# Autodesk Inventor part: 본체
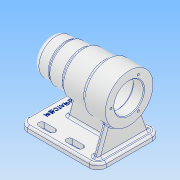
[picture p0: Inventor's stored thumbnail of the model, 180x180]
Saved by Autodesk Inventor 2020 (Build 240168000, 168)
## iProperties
Created: 2021-10
Part Number: 본체
Material: 알루미늄 6061
Document SubType Name: Modeling
Designer: user
Density: 2.7 g/cm^3
Appearance: 알루미늄 - 평지
Mass: 694.197 g
Surface Area: 698.877 cm^2
Volume: 257.11 cm^3
Author: user
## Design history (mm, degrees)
sketch "스케치1"
  geometry: L1 (0, 0)-(0, 25); L2 (0, 25)-(24, 25); L3 (112, 21)-(97, 21); L4 (97, 21)-(97, 21); L5 (94, 24)-(46, 24); L6 (43, 21)-(43, 21); L7 (43, 21)-(31.3, 21); L8 (31, 20.7)-(31, 17.5); L9 (31, 17.5)-(13.3, 17.5); L10 (13, 17.2)-(13, 16); L11 (13, 16)-(9.3, 16); L12 (9, 15.7)-(9, 10.5); L13 (9, 10.5)-(9, 10.5); L14 (6, 7.5)-(6, 0); L15 (6, 0)-(0, 0); L16 (24, 25)-(24, 27); L17 (24, 27)-(46, 27); L18 (46, 27)-(46, 30); L19 (80, 34)-(112, 34); L20 (112, 34)-(112, 21); L21 (46, 30)-(80, 30); L22 (80, 30)-(80, 34); A1 r 0.3 centre (9.3, 15.7) between (9.3, 16) and (9, 15.7); A2 r 0.3 centre (13.3, 17.2) between (13.3, 17.5) and (13, 17.2); A3 r 0.3 centre (31.3, 20.7) between (31.3, 21) and (31, 20.7); A4 r 3 centre (9, 7.5) between (9, 10.5) and (6, 7.5); A5 r 3 centre (46, 21) between (46, 24) and (43, 21); A6 r 3 centre (94, 21) between (97, 21) and (94, 24); 9 further points
  constraints: 44 end point, 14 perpendicular, 14 point on line, 12 point on circle, 12 tangent, 6 centre point, 4 equal radius, 3 vertical, 2 horizontal, 1 parallel
  dimensions: "d0" = 25 distance of L1.start L1.end; "d1" = 24 distance of L1.end L2.end; "d3" = 46 horizontal distance of L18.end L1.end; "d4" = 80 horizontal distance of L19.start L1.end; "d5" = 112 horizontal distance of L19.end L1.end; "d6" = 2 distance of L2.end L16.end; "d7" = 3 distance of L17.end L18.end; "d8" = 4 distance of L21.end L19.start; "d9" = 13 distance of L19.end L3.start; "d10" = 15 distance of L3.start L3.end; "d11" = 3 distance of L3.end point (97, 24); "d12" = 54 distance of point (97, 24) point (43, 24); "d13" = 24 distance from line of L14.end L5; "d14" = 10.5 distance of point (6, 10.5) L14.end; "d16" = 18 distance of L8.end point (13, 17.5); "d17" = 12 distance of L6.end point (31, 21); "d18" = 3 distance from line of L12.end L14; "d19" = 4 horizontal distance of L10.end L12.end; "d20" = 17.5 distance from line of L14.end L9; "d23" = 0.3 radius of A1; "d24" = 3 radius of A4; "d80" = 16 distance from line of L14.end L11
revolve "회전1" sketch "스케치1" stored, may be unused: angle "d22" = 90 deg
chamfer "모따기1" distance "d25" = 1; stored, may be unused: second distance "d26" = 2, angle "d27" = 45 deg
node "작업 평면1"
sketch "스케치2"
  geometry: L1 (0, -45)-(-112, -45); L2 (-112, -45)-(-112, 45); L3 (-112, 45)-(0, 45); L4 (0, 45)-(0, -45); L5 (-112, 34)-(-112, -34) reference; L6 (0, 25)-(0, -25) reference; 2 further points
  constraints: 8 end point, 2 parallel, 1 coincident, 1 collinear, 1 horizontal, 1 midpoint, 1 perpendicular
  dimensions: "d29" = 112 distance of L2.end L3.end; "d30" = 90 distance of L1.end L2.end
extrude "돌출1" join sketch "스케치2" distance "d31" = 8; taper "d32" = 0 deg
sketch "스케치3"
  geometry: L1 (104, 37)-(96, 37); L2 (96, 37)-(96, -37); L3 (96, -37)-(104, -37); L4 (104, -37)-(104, 37); L5 (104, 4)-(27, 4); L6 (27, 4)-(27, -4); L7 (27, -4)-(104, -4); L8 (104, -4)-(104, 4); L9 (112, -45)-(112, 45) reference; 3 further points
  constraints: 16 end point, 4 parallel, 2 horizontal, 2 perpendicular, 1 horizontal alignment, 1 midpoint, 1 point on line
  dimensions: "d33" = 8 distance between parallel lines of L4 L2; "d34" = 8 distance between parallel lines of L7 L5; "d35" = 8 distance between parallel lines of L9 L4; "d36" = 77 distance of L5.start L5.end; "d37" = 8 horizontal distance of L9.end L1.start; "d38" = 8 horizontal distance of L9.start L3.end
extrude "돌출2" join sketch "스케치3" stored distance "d39" = 8; taper "d40" = 0 deg
sketch "스케치4"
  geometry: L1 (-41, -8)-(-41, 0) reference; L2 (-41, 0)-(0, 0) reference; L3 (0, 0)-(0, 28.236) reference; L4 (8, 28.236)-(8, 0) reference; L5 (8, 0)-(49, 0) reference; L6 (49, 0)-(49, -8) reference; L7 (49, -8)-(-41, -8) reference; L8 (0, 0)-(8, 0) reference; L9 (-19.409, 37.342)-(-33, 0); C1 r 21 at (4, 62) reference; A1 r 34 centre (4, 62) between (8, 28.236) and (0, 28.236) reference; A2 r 34 centre (4, 62) between (0, 28.236) and (8, 28.236) reference; 1 further point
  constraints: 2 end point, 1 point on circle, 1 point on line
  dimensions: "d41" = 110 deg angle of L2 L9; "d42" = 8 distance of L1.end L9.end
extrude "돌출3" join sketch "스케치4" distance "d43" = 8; taper "d44" = 0 deg
sketch "스케치5"
  geometry: 2 further points
  constraints: 1 horizontal alignment
  dimensions: "d45" = 26 distance of point (0, 0) point (-26, 0)
hole "구멍1" sketch "스케치5" at (-26, 0) diameter "d46" = 3.242; stored, may be unused: countersink angle "d50" = 90 deg, drill point angle "d52" = 118 deg; dims "d47" = 8, "d48" = 4, "d49" = 2, "d51" = 11
fillet "모깎기1" dims "d56" = 8
fillet "모깎기2" dims "d57" = 3
fillet "모깎기6" dims "d61" = 12
fillet "모깎기7" dims "d62" = 3
sketch "스케치6"
  geometry: L1 (15.5, 33)-(39.5, 33); L2 (20, 37.5)-(35, 37.5); L3 (35, 28.5)-(20, 28.5); L4 (55.5, 33)-(79.5, 33); L5 (60, 37.5)-(75, 37.5); L6 (75, 28.5)-(60, 28.5); L7 (0, 33)-(0, -33) reference; A1 r 4.5 centre (20, 33) between (20, 37.5) and (20, 28.5); A2 r 4.5 centre (35, 33) between (35, 28.5) and (35, 37.5); A3 r 4.5 centre (60, 33) between (60, 37.5) and (60, 28.5); A4 r 4.5 centre (75, 33) between (75, 28.5) and (75, 37.5); 3 further points
  constraints: 16 end point, 12 point on circle, 8 tangent, 4 centre point, 4 point on line, 3 parallel, 2 midpoint, 1 horizontal, 1 horizontal alignment
  dimensions: "d64" = 15 distance of A2.centre A1.centre; "d65" = 15 distance of A4.centre A3.centre; "d66" = 25 distance of A3.centre A2.centre; "d67" = 20 distance from line of L7 A1.centre; "d68" = 4.5 radius of A4; "d69" = 4.5 radius of A2; "d70" = 33 vertical distance of point (0, 0) A1.centre
extrude "돌출4" cut sketch "스케치6" distance "d71" = 53.5; taper "d72" = 0 deg
sketch "스케치7"
  geometry: 2 further points
  constraints: 1 horizontal alignment, 1 other
  dimensions: "d73" = 12 distance of point (0, 0) point (12, 0)
feature "엠보싱1" sketch "스케치7" dims "d74" = 0.5, "d75" = 0
feature "면 기울기1" dims angle "d76" = 15 deg
fillet "모깎기8" dims "d77" = 3
fillet "모깎기9" dims "d78" = 3
node "솔리드1"
mirror "미러1"
pattern_circular "원형 패턴1" dims angle "d54" = 360 deg
mirror "미러2"
node "작업 평면2"
node "작업 평면3"
node "절단 모서리 투영1"
feature "A9D066F2-1C7D-4E18-AEED-F7BC21143FA4" dims "d46" = 3.242, "d47" = 8, "d48" = 4, "d49" = 2, "d50" = 90 deg, "d51" = 11, "d52" = 118 deg
